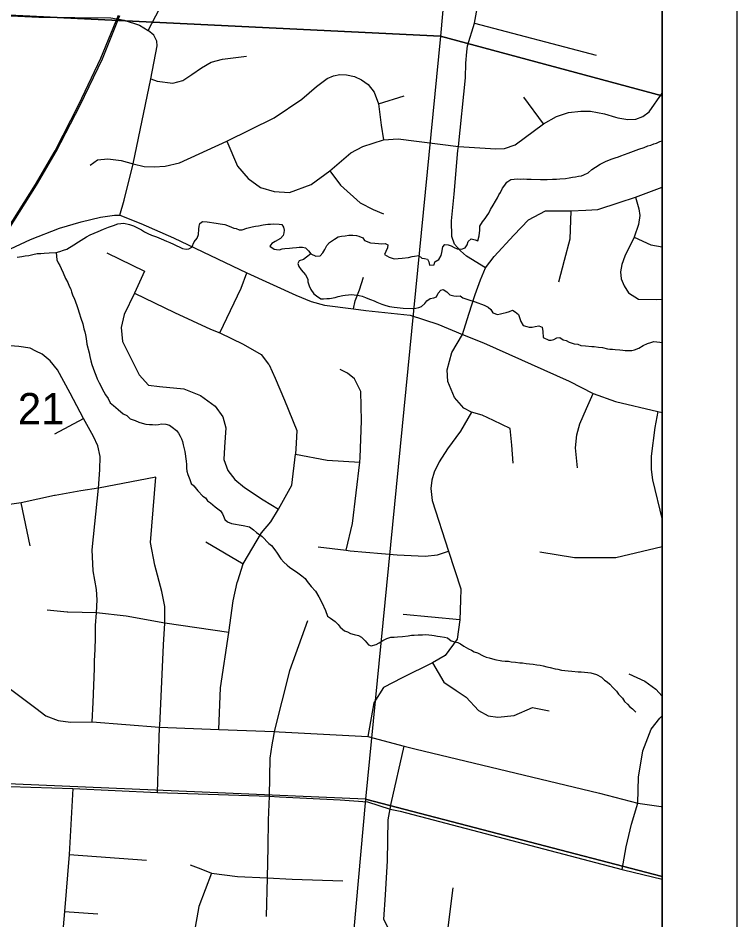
# Model space of a CAD drawing. Extents: x 0 to 34, y 0 to 22.
# Drawn here: x 8.039 to 9, y 15.851 to 17.056 of the extents above; entities that cross this region are included whole.
import ezdxf

# ---------------------------------------------------------------- set-up
doc = ezdxf.new("R2010")
doc.units = 0
for name, color, linetype in [('Default', 7, 'Continuous'), ('GM_X_Minor_River', 7, 'Continuous'), ('GM_X_Rail_Line', 7, 'Continuous'), ('GM_X_Section', 7, 'Continuous'), ('GM_X_Section_Text', 7, 'Continuous'), ('GM_X_Township_Road', 7, 'Continuous'), ('SH_Cut_Line', 7, 'Continuous'), ('SH_Data', 7, 'Continuous')]:
    doc.layers.add(name, color=color, linetype=linetype)

msp = doc.modelspace()

# ---------------------------------------------------------------- linework, layer by layer
at = {"layer": 'Default'}
for points in [[(8.9, 16.9525), (8.9, 17.9772), (8.6934, 18.0333), (8.604, 17.0319)], [(8.9, 15.9093), (8.9, 16.9525), (8.604, 17.0319), (8.5037, 16.0129)], [(8.9, 14.8605), (8.9, 15.9093), (8.5037, 16.0129), (8.4096, 14.9658)]]:
    msp.add_lwpolyline(points, close=True, dxfattribs=at)
at = {"layer": 'GM_X_Minor_River'}
for points in [[(8.6502, 16.7598), (8.6539, 16.7585), (8.6557, 16.7653), (8.6566, 16.7729), (8.6564, 16.7782), (8.66, 16.7842), (8.6636, 16.7886), (8.6663, 16.7923), (8.6683, 16.7957), (8.6707, 16.8006), (8.6743, 16.8065), (8.6772, 16.8118), (8.6799, 16.8159), (8.682, 16.82), (8.684, 16.8233), (8.6868, 16.829), (8.6899, 16.833), (8.6927, 16.8368), (8.6978, 16.8404), (8.7023, 16.841), (8.7069, 16.8413), (8.7107, 16.8412), (8.7141, 16.8414), (8.7194, 16.8409), (8.7251, 16.8411), (8.7377, 16.8407), (8.7464, 16.8408), (8.7536, 16.841), (8.759, 16.8412), (8.7632, 16.8415), (8.7708, 16.842), (8.7758, 16.843), (8.7803, 16.8436), (8.7842, 16.8442), (8.7884, 16.8449), (8.7922, 16.8455), (8.7956, 16.8469), (8.801, 16.8494), (8.8061, 16.8538), (8.8111, 16.8571), (8.817, 16.8611), (8.8243, 16.8647), (8.832, 16.8679), (8.8373, 16.8696), (8.8416, 16.871), (8.845, 16.8724), (8.8546, 16.8759), (8.8619, 16.8784), (8.8689, 16.8812), (8.8758, 16.8832), (8.8811, 16.8854), (8.885, 16.8864), (8.8888, 16.8882), (8.8923, 16.8892), (8.8969, 16.8913), (8.9, 16.8924)], [(8.038, 16.737), (8.0444, 16.7376), (8.049, 16.7386), (8.054, 16.7392), (8.0593, 16.7402), (8.0651, 16.7415), (8.07, 16.7418), (8.0742, 16.742), (8.0811, 16.7426), (8.0902, 16.743), (8.0952, 16.7444), (8.1002, 16.7462), (8.1044, 16.7475), (8.1137, 16.7533), (8.1203, 16.7573), (8.1307, 16.7638), (8.1357, 16.7667), (8.1465, 16.771), (8.1534, 16.7742), (8.1604, 16.777), (8.1669, 16.7791), (8.1727, 16.7812), (8.1769, 16.7818), (8.1807, 16.7821), (8.1882, 16.7803), (8.1935, 16.7787), (8.1991, 16.7762), (8.2044, 16.7734), (8.2085, 16.7706), (8.213, 16.7686), (8.2178, 16.7661), (8.2242, 16.764), (8.2306, 16.7612), (8.2377, 16.7583), (8.2422, 16.7563), (8.2471, 16.7542), (8.2505, 16.7526), (8.2557, 16.7501), (8.2591, 16.7485), (8.264, 16.7476), (8.2675, 16.7479), (8.2717, 16.75), (8.2746, 16.7572)], [(8.2746, 16.7572), (8.2789, 16.762), (8.2806, 16.7672), (8.2811, 16.7741), (8.2816, 16.7782), (8.2821, 16.7816), (8.286, 16.7846), (8.2921, 16.784), (8.3042, 16.7821), (8.3095, 16.7812), (8.3155, 16.7806), (8.3216, 16.7782), (8.3276, 16.7757), (8.331, 16.7752), (8.3347, 16.7732), (8.3389, 16.7734), (8.345, 16.7755), (8.3523, 16.7772), (8.3565, 16.7782), (8.3607, 16.7789), (8.3668, 16.7802), (8.3733, 16.7808), (8.3768, 16.781), (8.3809, 16.7813), (8.3885, 16.7811), (8.3919, 16.7806), (8.3941, 16.7771), (8.3951, 16.7729), (8.3947, 16.7695), (8.3938, 16.7657), (8.3899, 16.7616), (8.3829, 16.7577), (8.3787, 16.7551), (8.3759, 16.7514), (8.3815, 16.7474), (8.3849, 16.747), (8.3887, 16.7468), (8.3921, 16.7479), (8.3959, 16.7485), (8.402, 16.7487), (8.4059, 16.7494), (8.4116, 16.7499), (8.415, 16.7502), (8.4196, 16.7501), (8.4233, 16.7492), (8.4274, 16.7453), (8.4307, 16.7414), (8.4375, 16.7381), (8.4432, 16.7387), (8.4467, 16.7428), (8.4495, 16.7469), (8.4519, 16.7525), (8.4555, 16.7562), (8.4621, 16.7609), (8.4671, 16.7638), (8.4717, 16.7648), (8.4763, 16.7654), (8.4812, 16.7661), (8.4865, 16.7663), (8.4915, 16.7657), (8.4949, 16.7649), (8.5001, 16.7628), (8.5023, 16.7593), (8.5102, 16.756), (8.5159, 16.7555), (8.5208, 16.755), (8.5246, 16.7548), (8.5299, 16.7551), (8.5337, 16.7531), (8.5332, 16.7493), (8.5308, 16.7444), (8.5291, 16.7406), (8.5351, 16.7367), (8.5419, 16.7346), (8.5525, 16.7354), (8.5609, 16.7363), (8.5659, 16.7376), (8.5693, 16.7383), (8.5751, 16.7389), (8.5788, 16.7357), (8.5826, 16.7352), (8.5867, 16.7343), (8.5881, 16.7305), (8.5891, 16.7263), (8.5952, 16.7265), (8.5965, 16.7306), (8.6015, 16.7339), (8.6047, 16.7391), (8.6056, 16.7429), (8.6069, 16.7504), (8.6097, 16.7538), (8.6139, 16.7533), (8.618, 16.752), (8.6221, 16.7496), (8.6263, 16.7479), (8.6319, 16.7474), (8.6369, 16.7495), (8.6393, 16.7532), (8.641, 16.7578), (8.6449, 16.7611), (8.6502, 16.7598)], [(8.0902, 16.743), (8.0911, 16.7331), (8.0932, 16.7293), (8.0954, 16.7258), (8.0972, 16.7215), (8.0997, 16.7161), (8.1029, 16.7081), (8.1058, 16.703), (8.1079, 16.698), (8.1097, 16.6942), (8.1107, 16.6907), (8.1128, 16.6853), (8.1143, 16.6819), (8.116, 16.6772), (8.1178, 16.6722), (8.1192, 16.6684), (8.1209, 16.6626), (8.1234, 16.6553), (8.1258, 16.6477), (8.1275, 16.6412), (8.1285, 16.6369), (8.1296, 16.6331), (8.1302, 16.6282), (8.1315, 16.6205), (8.1342, 16.609), (8.1355, 16.604), (8.1365, 16.5983), (8.1379, 16.5933), (8.1397, 16.5887), (8.1414, 16.5837), (8.1432, 16.5791), (8.1453, 16.5741), (8.1478, 16.5691), (8.15, 16.5648), (8.1518, 16.561), (8.1539, 16.5567), (8.1561, 16.5528), (8.1597, 16.5478), (8.1626, 16.5424), (8.1667, 16.5388), (8.173, 16.5333), (8.1797, 16.5274), (8.1849, 16.5254), (8.189, 16.521), (8.1958, 16.5186), (8.2006, 16.5165), (8.2052, 16.5149), (8.2101, 16.5139), (8.215, 16.5134), (8.2192, 16.5133), (8.223, 16.5128), (8.2272, 16.5134), (8.231, 16.5141), (8.2367, 16.5139), (8.2419, 16.5122), (8.2453, 16.5098), (8.2509, 16.5051), (8.2538, 16.5016), (8.256, 16.4977), (8.2578, 16.4942), (8.2592, 16.4904), (8.2602, 16.4862), (8.2622, 16.477), (8.2641, 16.4644), (8.2644, 16.4598), (8.2646, 16.4549), (8.2649, 16.4507), (8.2662, 16.4465), (8.2687, 16.4399), (8.2708, 16.4345), (8.2742, 16.4314), (8.2797, 16.4248), (8.2863, 16.4177), (8.2897, 16.4153), (8.2926, 16.4114), (8.2967, 16.4087), (8.3026, 16.4032), (8.3063, 16.4004), (8.3097, 16.398), (8.3126, 16.3941), (8.314, 16.3906), (8.3158, 16.3864), (8.3191, 16.3833), (8.3248, 16.3812), (8.3403, 16.3784), (8.3486, 16.3767), (8.3542, 16.3723), (8.3579, 16.3691), (8.3657, 16.3636), (8.3745, 16.3542), (8.3779, 16.3514), (8.3823, 16.346), (8.3856, 16.3413), (8.3907, 16.3339), (8.3947, 16.3292), (8.3988, 16.3253), (8.4021, 16.3226), (8.4081, 16.3186), (8.4114, 16.3162), (8.4152, 16.3138), (8.4185, 16.311)], [(8.4307, 16.7414), (8.4249, 16.7366), (8.421, 16.7337), (8.4152, 16.732), (8.4132, 16.7282), (8.4146, 16.7244), (8.4175, 16.7201), (8.4234, 16.7131), (8.4267, 16.7073), (8.4266, 16.7039), (8.4283, 16.6985), (8.4304, 16.6935), (8.4345, 16.688), (8.4382, 16.6853), (8.4438, 16.6813), (8.4476, 16.6812), (8.4518, 16.6814), (8.4556, 16.6817), (8.4632, 16.683), (8.467, 16.6844), (8.4732, 16.6857), (8.4766, 16.686), (8.4808, 16.6866), (8.4854, 16.6869), (8.4952, 16.6858), (8.4994, 16.6845), (8.5035, 16.6829), (8.5069, 16.6816), (8.5103, 16.6804), (8.5151, 16.6783), (8.5189, 16.6767), (8.5256, 16.6738), (8.5309, 16.6722), (8.5358, 16.6709), (8.5419, 16.6699), (8.554, 16.6688), (8.5662, 16.6684), (8.5711, 16.6687), (8.5749, 16.6697), (8.5784, 16.6707), (8.5831, 16.6748), (8.5855, 16.6785), (8.5901, 16.6814), (8.5951, 16.6827), (8.5985, 16.6838), (8.6006, 16.6887), (8.6041, 16.6927), (8.6076, 16.6934), (8.6124, 16.6906), (8.6165, 16.6863), (8.6218, 16.685), (8.6256, 16.6849), (8.6301, 16.6851), (8.6339, 16.6827), (8.6402, 16.6802), (8.65, 16.6773), (8.6538, 16.6756), (8.6587, 16.674), (8.6621, 16.6727), (8.6677, 16.6699), (8.671, 16.6671), (8.6739, 16.6625), (8.6799, 16.6604), (8.6841, 16.661), (8.6876, 16.6621), (8.6914, 16.6627), (8.696, 16.6641), (8.6999, 16.6659), (8.7036, 16.6638), (8.7081, 16.6603), (8.7098, 16.6549), (8.7112, 16.6507), (8.7141, 16.6457), (8.719, 16.644), (8.7224, 16.6435), (8.7262, 16.6434), (8.7304, 16.644), (8.7354, 16.645), (8.7395, 16.6434), (8.7405, 16.6373), (8.741, 16.6296), (8.7485, 16.626), (8.7519, 16.6259), (8.7554, 16.6269), (8.7592, 16.6291), (8.7634, 16.6293), (8.7679, 16.6265), (8.772, 16.6253), (8.7758, 16.6232), (8.7826, 16.6211), (8.7875, 16.6206), (8.7912, 16.619), (8.7977, 16.6184), (8.806, 16.6174), (8.8094, 16.6173), (8.8151, 16.6167), (8.8204, 16.6162), (8.8268, 16.6145), (8.8302, 16.614), (8.8337, 16.6139), (8.8374, 16.6134)], [(8.8374, 16.6134), (8.8435, 16.6132), (8.8473, 16.6127), (8.8507, 16.6122), (8.8541, 16.6121), (8.8595, 16.6123), (8.8629, 16.613), (8.8687, 16.6151), (8.8745, 16.6187), (8.8806, 16.6216), (8.8849, 16.623), (8.8891, 16.624), (8.8929, 16.6238), (8.897, 16.6233), (8.9, 16.6227)], [(8.4185, 16.311), (8.423, 16.3075), (8.4255, 16.3036), (8.431, 16.2966), (8.4369, 16.2907), (8.4413, 16.283), (8.4452, 16.2756), (8.4502, 16.2648), (8.453, 16.2571), (8.4571, 16.2543), (8.4631, 16.25), (8.4672, 16.2461), (8.4697, 16.2426), (8.4757, 16.2378), (8.4798, 16.2362), (8.4835, 16.2342), (8.4884, 16.2329), (8.4941, 16.2315), (8.4982, 16.2291), (8.5034, 16.224), (8.5078, 16.219), (8.5112, 16.2177), (8.5177, 16.2194), (8.5219, 16.2216), (8.527, 16.2248), (8.532, 16.2274), (8.5374, 16.2291), (8.5419, 16.2293), (8.5465, 16.2296), (8.553, 16.2301), (8.5606, 16.2307), (8.5652, 16.2317), (8.5686, 16.2319), (8.5739, 16.2322), (8.58, 16.2323), (8.5842, 16.2326), (8.5884, 16.2321), (8.5922, 16.2316), (8.5956, 16.2315), (8.5997, 16.2306), (8.6032, 16.2301), (8.6092, 16.2292), (8.6134, 16.2283), (8.6182, 16.2243), (8.6231, 16.223), (8.6269, 16.2218), (8.6306, 16.2202), (8.6351, 16.217), (8.6411, 16.2134), (8.6452, 16.2117), (8.6489, 16.2097), (8.6534, 16.2081), (8.6609, 16.2044), (8.6651, 16.2024), (8.6688, 16.2015), (8.6764, 16.1994), (8.6858, 16.1976), (8.6904, 16.197), (8.6949, 16.1969), (8.6983, 16.196), (8.704, 16.1959), (8.7097, 16.1949), (8.7135, 16.1948), (8.7184, 16.1939), (8.7229, 16.1934), (8.7279, 16.1932), (8.7324, 16.1923), (8.737, 16.1918), (8.7411, 16.1909), (8.746, 16.1896), (8.7502, 16.1887), (8.757, 16.187), (8.7608, 16.1865), (8.7657, 16.1852), (8.7702, 16.1847), (8.7744, 16.1842), (8.7793, 16.1837), (8.788, 16.183), (8.7918, 16.1829), (8.8009, 16.1819), (8.8047, 16.1814), (8.8122, 16.1792), (8.819, 16.1756), (8.823, 16.1717), (8.8264, 16.1693), (8.8301, 16.1665), (8.8342, 16.1619), (8.8389, 16.1568), (8.8415, 16.1529), (8.847, 16.1478), (8.8496, 16.1431), (8.8536, 16.1396), (8.857, 16.1361), (8.8603, 16.1333), (8.8647, 16.129)]]:
    msp.add_lwpolyline(points, dxfattribs=at)
at = {"layer": 'GM_X_Rail_Line'}
for points in [[(8.0247, 16.774), (8.0625, 16.834), (8.0888, 16.879), (8.1205, 16.9408), (8.1502, 17.0028), (8.1738, 17.0603)], [(8.0263, 16.7729), (8.0641, 16.833), (8.0905, 16.8781), (8.1222, 16.9399), (8.152, 17.002), (8.1756, 17.0596)]]:
    msp.add_lwpolyline(points, dxfattribs=at)
at = {"layer": 'GM_X_Section'}
for points in [[(7.7014, 18.1225), (8.6934, 18.0333), (8.604, 17.0319), (7.6063, 17.081)], [(8.604, 17.0319), (8.5037, 16.0129), (7.5157, 16.0549), (7.6063, 17.081)]]:
    msp.add_lwpolyline(points, close=True, dxfattribs=at)
at = {"layer": 'GM_X_Township_Road'}
for p, q in [((8.6495, 17.0495), (8.8118, 17.0066)), ((8.5208, 16.9418), (8.5554, 16.9523)), ((8.7414, 16.915), (8.7153, 16.9507)), ((8.8646, 16.8168), (8.9, 16.8303)), ((8.158, 16.7428), (8.2084, 16.7181)), ((8.0887, 16.5006), (8.1268, 16.5214)), ((8.0554, 16.351), (8.0436, 16.4088)), ((8.2905, 16.3567), (8.3404, 16.3271)), ((8.1052, 16.2625), (8.0785, 16.2653)), ((8.6295, 16.2521), (8.5539, 16.2595)), ((8.1076, 15.9389), (8.211, 15.9313)), ((8.1015, 15.8627), (8.1461, 15.8593))]:
    msp.add_line(p, q, dxfattribs=at)
for points in [[(5.9659, 15.1626), (6.3032, 15.1064), (6.401, 15.0917), (6.488, 15.0839), (6.9119, 15.0636), (7.3636, 15.0306), (7.437, 15.0262), (7.6301, 15.0148), (7.6752, 15.0122), (8.168, 14.9819), (8.3833, 14.9688), (8.525, 14.938), (8.5293, 14.9371), (8.9, 14.8595), (8.9, 19.9667)], [(8.1756, 16.7928), (8.1812, 16.813), (8.193, 16.8615), (8.2167, 16.975), (8.2254, 17.0193), (8.225, 17.0253), (8.2207, 17.0336), (8.2133, 17.0395), (8.2282, 17.0688), (8.2382, 17.0839), (8.3027, 17.1868), (8.3125, 17.2065), (8.3299, 17.2418), (8.3405, 17.276), (8.3523, 17.3455)], [(8.639, 17.011), (8.6398, 17.019), (8.6495, 17.0495), (8.6547, 17.0788), (8.6573, 17.0941), (8.6558, 17.1126), (8.6524, 17.1297), (8.6506, 17.1375), (8.6469, 17.1516), (8.6435, 17.1624), (8.6465, 17.1913), (8.6489, 17.2272), (8.6477, 17.2476)], [(7.6462, 17.1828), (7.6497, 17.1758), (7.6694, 17.134), (7.6846, 17.1052), (7.7014, 17.0885), (7.7222, 17.077), (7.7485, 17.0713), (7.9163, 17.0648), (8.0673, 17.0576), (8.1632, 17.0565), (8.1812, 17.0533), (8.2017, 17.0469), (8.2133, 17.0395)], [(8.2167, 16.975), (8.2252, 16.9719), (8.2461, 16.9693), (8.2594, 16.9727), (8.2715, 16.9808), (8.2846, 16.9898), (8.2975, 16.9973), (8.3126, 17.0012), (8.3447, 17.0053)], [(8.6638, 16.7227), (8.6387, 16.738), (8.6304, 16.7453), (8.6227, 16.7541), (8.6189, 16.7645), (8.6185, 16.7854), (8.6223, 16.8211), (8.6272, 16.8794), (8.6278, 16.8848), (8.6372, 16.9763), (8.6376, 16.996), (8.639, 17.011)], [(8.193, 16.8615), (8.2078, 16.8579), (8.2212, 16.8575), (8.236, 16.8583), (8.2553, 16.8627), (8.3182, 16.8917), (8.3814, 16.9229), (8.4184, 16.9478), (8.4381, 16.965), (8.4526, 16.9757), (8.4609, 16.9791), (8.4692, 16.9809), (8.4782, 16.9805), (8.489, 16.9781), (8.4985, 16.9737), (8.5071, 16.9676), (8.5153, 16.9571), (8.5208, 16.9418), (8.5246, 16.9133), (8.5277, 16.8937)], [(8.8378, 16.9239), (8.8406, 16.9231), (8.8544, 16.9207), (8.8649, 16.9214), (8.874, 16.9249), (8.8827, 16.931), (8.9, 16.9558)], [(8.3182, 16.8917), (8.3328, 16.8586), (8.347, 16.8417), (8.3633, 16.8297), (8.3818, 16.8244), (8.4022, 16.8234), (8.4311, 16.8341), (8.4561, 16.852), (8.4841, 16.8761), (8.5, 16.8848), (8.5277, 16.8937), (8.5473, 16.8949), (8.6278, 16.8848), (8.678, 16.8815), (8.6892, 16.8821), (8.7036, 16.8869), (8.7414, 16.915), (8.7589, 16.9249), (8.775, 16.9301), (8.7912, 16.9321), (8.8041, 16.9319), (8.8229, 16.9283), (8.8378, 16.9239)], [(8.1358, 16.8596), (8.1456, 16.8667), (8.1594, 16.8682), (8.1772, 16.8658), (8.193, 16.8615)], [(8.4561, 16.852), (8.4702, 16.833), (8.4963, 16.8093), (8.5138, 16.8003), (8.5277, 16.7945)], [(8.6334, 16.6336), (8.6419, 16.6607), (8.65, 16.6868), (8.6575, 16.7065), (8.6638, 16.7227), (8.6757, 16.7377), (8.7017, 16.7661), (8.7214, 16.7866), (8.7443, 16.7988), (8.7778, 16.7989), (8.7979, 16.7996), (8.814, 16.8004), (8.8427, 16.8097), (8.8646, 16.8168)], [(8.8646, 16.8168), (8.869, 16.8015), (8.8702, 16.7926), (8.8684, 16.7804), (8.8628, 16.7636), (8.8502, 16.738), (8.846, 16.727)], [(8.7778, 16.7989), (8.7765, 16.7608), (8.769, 16.7325), (8.7615, 16.7035)], [(8.0293, 16.7478), (8.0562, 16.7603), (8.0949, 16.7756), (8.1235, 16.7842), (8.1497, 16.7902), (8.1681, 16.793), (8.1756, 16.7928), (8.2036, 16.7818), (8.2473, 16.7628), (8.3451, 16.7161), (8.4105, 16.686), (8.4312, 16.6774), (8.4489, 16.6727), (8.4876, 16.6677), (8.5043, 16.6655), (8.5635, 16.6593), (8.6004, 16.6475), (8.6334, 16.6336), (8.6611, 16.6223), (8.7757, 16.5712), (8.8078, 16.5548), (8.8377, 16.5441), (8.8942, 16.5307), (8.9, 16.5293)], [(8.8628, 16.7636), (8.8849, 16.7531), (8.9, 16.7506)], [(8.846, 16.727), (8.8446, 16.7173), (8.8453, 16.7079), (8.8495, 16.6984), (8.8551, 16.6893), (8.8684, 16.6809), (8.8922, 16.6802), (8.9, 16.6809)], [(8.2084, 16.7181), (8.195, 16.6886), (8.1813, 16.6601), (8.1773, 16.6427), (8.1789, 16.624), (8.2011, 16.5795), (8.2137, 16.5657), (8.2286, 16.5638), (8.2607, 16.5607), (8.2833, 16.5519), (8.3028, 16.5379), (8.3128, 16.5234), (8.3168, 16.5089), (8.3152, 16.483), (8.3142, 16.4663), (8.3197, 16.4518), (8.329, 16.4397), (8.3421, 16.429), (8.3668, 16.4128), (8.3872, 16.4)], [(8.3092, 16.6359), (8.3374, 16.6956), (8.3451, 16.7161)], [(8.4876, 16.6677), (8.4898, 16.6784), (8.4955, 16.693), (8.5008, 16.7101)], [(8.195, 16.6886), (8.2486, 16.6628), (8.2964, 16.6406), (8.3092, 16.6359), (8.3401, 16.6206), (8.3644, 16.6066), (8.3742, 16.5939)], [(8.7008, 16.4618), (8.6992, 16.4857), (8.6971, 16.5078), (8.6748, 16.5187), (8.6594, 16.5257), (8.6455, 16.5296), (8.6349, 16.5349), (8.6226, 16.5493), (8.6138, 16.5709), (8.6129, 16.5865), (8.6188, 16.6093), (8.6334, 16.6336)], [(8.063, 16.6114), (8.0554, 16.6151), (8.0404, 16.6176), (8.0234, 16.6188)], [(8.1418, 16.2031), (8.1428, 16.2258), (8.1428, 16.2448), (8.1442, 16.2616), (8.1451, 16.2789), (8.1442, 16.2927), (8.1399, 16.3176), (8.1384, 16.346), (8.1469, 16.4282), (8.1487, 16.4529), (8.1493, 16.4703), (8.1458, 16.4846), (8.14, 16.4972), (8.1268, 16.5214), (8.109, 16.5552), (8.092, 16.5864), (8.0824, 16.5984), (8.0716, 16.6073), (8.063, 16.6114)], [(8.3742, 16.5939), (8.3749, 16.5931), (8.3829, 16.575), (8.3956, 16.5457), (8.4117, 16.5051), (8.4112, 16.4882), (8.4101, 16.4737)], [(8.4776, 16.3453), (8.4862, 16.3812), (8.4959, 16.4629), (8.4967, 16.4692), (8.4981, 16.5183), (8.4974, 16.5575), (8.489, 16.5743), (8.4797, 16.5818), (8.47, 16.5867)], [(8.7868, 16.4555), (8.7843, 16.4822), (8.7861, 16.4993), (8.79, 16.5143), (8.7988, 16.5348), (8.8078, 16.5548)], [(8.6455, 16.5296), (8.6304, 16.5042), (8.613, 16.4806), (8.6021, 16.4635), (8.5952, 16.4497), (8.5923, 16.4389), (8.5909, 16.4279), (8.5926, 16.4116), (8.6146, 16.3442), (8.6309, 16.2935), (8.6304, 16.2784)], [(8.8942, 16.5307), (8.8903, 16.5092), (8.8852, 16.4709), (8.8853, 16.453), (8.887, 16.4395), (8.9, 16.3859)], [(8.3329, 16.3042), (8.3404, 16.3271), (8.3646, 16.3686), (8.377, 16.3833), (8.3872, 16.4), (8.4051, 16.4323), (8.4101, 16.4737)], [(8.4101, 16.4737), (8.4524, 16.4657), (8.4959, 16.4629)], [(8.2234, 16.4429), (8.1469, 16.4282), (8.1233, 16.4245), (8.0889, 16.4184)], [(8.2256, 16.0218), (8.2286, 16.109), (8.2288, 16.1105), (8.2337, 16.2188), (8.2354, 16.2477), (8.2356, 16.2702), (8.2314, 16.2902), (8.222, 16.3251), (8.2163, 16.3554), (8.2234, 16.4429)], [(8.0889, 16.4184), (8.088, 16.4182), (8.0436, 16.4088), (8.0025, 16.4029)], [(8.4403, 16.3499), (8.4776, 16.3453), (8.4831, 16.3446), (8.5459, 16.3392), (8.5832, 16.3374), (8.5998, 16.3391), (8.6146, 16.3442)], [(8.9, 16.35), (8.838, 16.3351), (8.7831, 16.3351), (8.7365, 16.3426)], [(8.3078, 16.1059), (8.31, 16.1615), (8.3211, 16.2355), (8.3266, 16.2778), (8.3323, 16.3023), (8.3329, 16.3042)], [(8.6304, 16.2784), (8.6295, 16.2521), (8.626, 16.2265), (8.6099, 16.2048), (8.5931, 16.195), (8.5525, 16.1747), (8.5279, 16.162), (8.515, 16.1414), (8.5068, 16.0962)], [(7.6388, 16.2603), (7.7896, 16.26), (7.9434, 16.2596), (7.953, 16.2593), (7.9581, 16.2577), (7.9611, 16.2542), (7.9621, 16.2512), (7.9609, 16.2326), (7.9543, 16.1713), (7.9462, 16.0935), (7.9436, 16.0321), (8.1128, 16.0269), (8.2256, 16.0218), (8.3748, 16.0166), (8.3889, 16.0157), (8.4699, 16.0118), (8.5061, 16.0093), (8.5367, 15.9995), (8.5499, 15.9965), (8.8465, 15.9189), (8.8484, 15.9184), (8.9, 15.906)], [(8.3211, 16.2355), (8.2354, 16.2477), (8.1837, 16.2573), (8.1442, 16.2616), (8.106, 16.2624), (8.1052, 16.2625)], [(8.4261, 16.2508), (8.4021, 16.184), (8.3815, 16.103), (8.3805, 16.0971)], [(8.1383, 16.1158), (8.1397, 16.1419), (8.1414, 16.1872), (8.1416, 16.1992), (8.1418, 16.2031)], [(8.5931, 16.195), (8.6085, 16.1691), (8.6246, 16.1578), (8.6383, 16.1491), (8.6548, 16.1312), (8.6677, 16.1242), (8.6803, 16.1221), (8.7024, 16.1246), (8.7266, 16.1351), (8.749, 16.1305)], [(7.9543, 16.1713), (7.9886, 16.1687), (8.0103, 16.1652), (8.0293, 16.1595), (8.0631, 16.1341), (8.0765, 16.1241), (8.0929, 16.1177), (8.1094, 16.1156), (8.1383, 16.1158), (8.2286, 16.109), (8.3078, 16.1059), (8.3815, 16.103), (8.3885, 16.1028), (8.5068, 16.0962), (8.5555, 16.0835), (8.5696, 16.0798), (8.8164, 16.0206), (8.8677, 16.0074), (8.8988, 16.0028), (8.9, 16.0027)], [(8.8555, 16.1802), (8.8769, 16.1704), (8.8918, 16.1597), (8.9, 16.1502)], [(8.8465, 15.9189), (8.8521, 15.9488), (8.8592, 15.9793), (8.8677, 16.0074), (8.8685, 16.042), (8.8743, 16.0771), (8.8854, 16.106), (8.897, 16.1207), (8.9, 16.1241)], [(8.3805, 16.0971), (8.3787, 16.0851), (8.3759, 16.0673), (8.3748, 16.0166), (8.3734, 15.9845), (8.3732, 15.9492), (8.3722, 15.9074), (8.3708, 15.856)], [(8.5358, 15.9947), (8.5367, 15.9995), (8.5381, 16.0068), (8.5555, 16.0835)], [(8.1128, 16.0269), (8.1076, 15.9389), (8.1015, 15.8627), (8.0946, 15.7854)], [(8.6097, 15.8056), (8.5563, 15.8204), (8.5395, 15.8302), (8.5283, 15.8519), (8.5304, 15.8848), (8.5332, 15.9304), (8.5339, 15.9851), (8.5358, 15.9947)], [(8.2695, 15.9251), (8.2834, 15.9197), (8.2979, 15.914), (8.3327, 15.9092), (8.3722, 15.9074), (8.4056, 15.906), (8.4734, 15.9036)], [(8.2979, 15.914), (8.281, 15.8692), (8.2748, 15.8343)], [(8.4569, 15.6412), (8.4855, 15.6346), (8.5199, 15.6613), (8.5521, 15.7026), (8.5956, 15.751), (8.6082, 15.793), (8.6097, 15.8056), (8.6208, 15.894)]]:
    msp.add_lwpolyline(points, dxfattribs=at)
at = {"layer": 'SH_Cut_Line'}
msp.add_lwpolyline([(5.9659, 15.1626), (6.3032, 15.1064), (6.401, 15.0917), (6.488, 15.0839), (6.9119, 15.0636), (7.3636, 15.0306), (7.437, 15.0262), (7.6301, 15.0148), (7.6752, 15.0122), (8.168, 14.9819), (8.3833, 14.9688), (8.525, 14.938), (8.5293, 14.9371), (8.9, 14.8595), (8.9, 20.9)], dxfattribs=at)
at = {"layer": 'SH_Data'}
for p, q in [((9, 21), (9, 14)), ((8.9, 20.9), (8.9, 14.1))]:
    msp.add_line(p, q, dxfattribs=at)

# ---------------------------------------------------------------- texts
at = {"layer": 'GM_X_Section_Text'}
msp.add_text('21', height=0.04186, rotation=0, dxfattribs=at).set_placement((8.0391, 16.5135))

doc.saveas('drawing.dxf')
